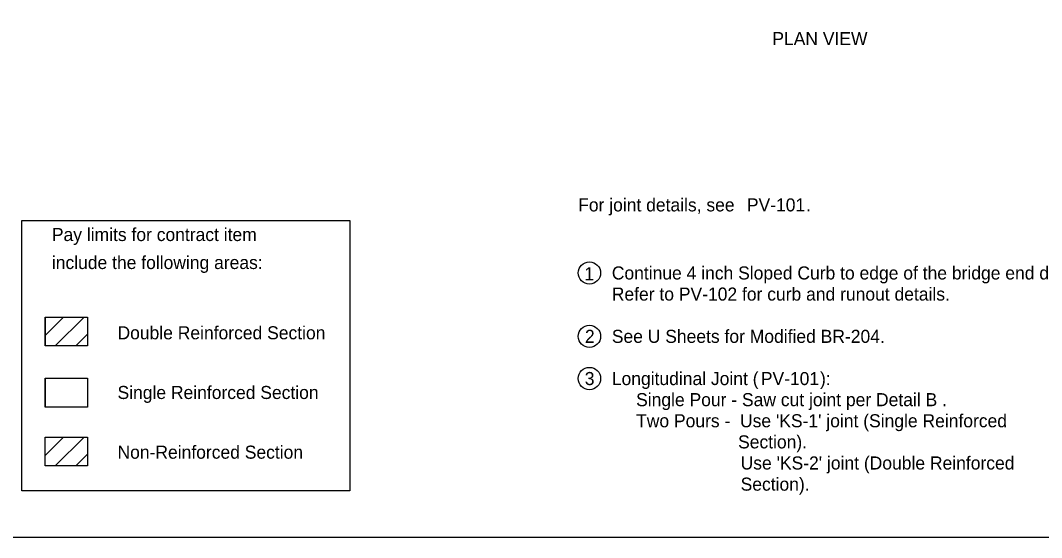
# Model space of a CAD drawing. Extents: x 9234 to 81668, y 5635 to 15999.
# Drawn here: x 21661 to 23096, y 13780 to 14508 of the extents above; entities that cross this region are included whole.
import ezdxf

# ---------------------------------------------------------------- set-up
doc = ezdxf.new("R2010")
doc.units = 0
for name, color, linetype in [('Level 61', 7, 'Continuous'), ('PS_BOLT', 7, 'Continuous'), ('PS_DIM', 7, 'Continuous')]:
    doc.layers.add(name, color=color, linetype=linetype)

msp = doc.modelspace()

# ---------------------------------------------------------------- linework, layer by layer
at = {"layer": 'Level 61'}
msp.add_lwpolyline([(21596.3, 15800.4), (24731.3, 15800.4), (24731.3, 13780.4), (21596.3, 13780.4)], close=True, dxfattribs=at)
at = {"layer": 'PS_BOLT'}
for p, q in [((21695.5, 14090.7), (21755.2, 14090.7)), ((21695.5, 14050.2), (21695.5, 14090.7)), ((21755.2, 14090.7), (21755.2, 14050.2)), ((21755.2, 14050.2), (21695.5, 14050.2)), ((21695.5, 14004.6), (21755.2, 14004.6)), ((21695.5, 13964.1), (21695.5, 14004.6)), ((21755.2, 14004.6), (21755.2, 13964.1)), ((21755.2, 13964.1), (21695.5, 13964.1))]:
    msp.add_line(p, q, dxfattribs=at)
at = {"layer": 'PS_DIM'}
for p, q in [((21695.5, 14090.7), (21755.2, 14090.7)), ((21695.5, 14090.7), (21695.5, 14050.2)), ((21695.5, 14065), (21721.1, 14090.7)), ((21709.7, 14050.2), (21750.2, 14090.7)), ((21755.2, 14090.7), (21755.2, 14050.2)), ((21738.8, 14050.2), (21755.2, 14066.6)), ((21755.2, 14050.2), (21695.5, 14050.2)), ((21695.5, 14004.6), (21755.2, 14004.6)), ((21695.5, 14004.6), (21695.5, 13964.1)), ((21755.2, 14004.6), (21755.2, 13964.1)), ((21755.2, 13964.1), (21695.5, 13964.1)), ((21695.5, 13896), (21721.1, 13921.6)), ((21709.7, 13881.2), (21750.2, 13921.6)), ((21738.8, 13881.2), (21755.2, 13897.6))]:
    msp.add_line(p, q, dxfattribs=at)
for points in [[(21662.7, 14226.7), (22124, 14226.7), (22124, 13846.4), (21662.7, 13846.4)], [(21695.5, 13921.6), (21755.2, 13921.6), (21755.2, 13881.2), (21695.5, 13881.2)]]:
    msp.add_lwpolyline(points, close=True, dxfattribs=at)
for centre in [(22460.7, 14152.8), (22460.7, 14063.6), (22460.7, 14004.2)]:
    msp.add_circle(centre, 15.7, dxfattribs=at)

# ---------------------------------------------------------------- texts
at = {"layer": 'PS_BOLT'}
for s, height, p in [('PLAN VIEW', 18.37, (22717.9, 14473.4)), ('For joint details, see ', 18.375, (22444.9, 14239.4)), ('PV-101', 18.37, (22682.1, 14239.4)), ('PV-101', 18.37, (22682.1, 14239.4)), ('.', 18.4, (22765.4, 14239.4)), ('Pay limits for contract item', 18.375, (21704.9, 14197.7)), ('include the following areas:', 18.375, (21704.9, 14158.3)), ('1', 18.4, (22453.5, 14142.5)), ('Continue 4 inch Sloped Curb to edge of the bridge end drain.', 18.375, (22492.2, 14143.6)), ('Refer to PV-102 for curb and runout details.', 18.375, (22492.2, 14113.9)), ('Double Reinforced Section', 18.375, (21797.2, 14059.4)), ('2', 18.4, (22454.4, 14054.4)), ('See U Sheets for Modified BR-204.', 18.375, (22492.2, 14054.4)), ('3', 18.4, (22454.2, 13995)), ('Longitudinal Joint (', 18.375, (22492.2, 13995)), ('PV-101', 18.37, (22701.7, 13995)), ('PV-101', 18.37, (22701.7, 13995)), ('):', 18.37, (22784.9, 13995)), ('Single Reinforced Section', 18.375, (21797.2, 13975.4)), ('     Single Pour - Saw cut joint per Detail B .', 18.375, (22492.2, 13965.3)), ("     Two Pours -  Use 'KS-1' joint (Single Reinforced", 18.375, (22492.2, 13935.6)), ('                          Section).', 18.375, (22492.2, 13905.9)), ('Non-Reinforced Section', 18.375, (21797.2, 13891.4)), ("     Use 'KS-2' joint (Double Reinforced", 18.375, (22639.2, 13876.2)), ('     Section).', 18.375, (22639.2, 13846.4))]:
    msp.add_text(s, height=height, dxfattribs=at).set_placement(p)

doc.saveas('drawing.dxf')
